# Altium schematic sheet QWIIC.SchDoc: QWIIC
size A3; Author: Silvio Navaretti; CompanyName: ARDUINO; DrawnBy: Silvio Navaretti; Engineer: Silvio Navaretti; Organization: ARDUINO; SheetNumber: 13; SheetTotal: 51; RevAuthor: Silvio Navaretti
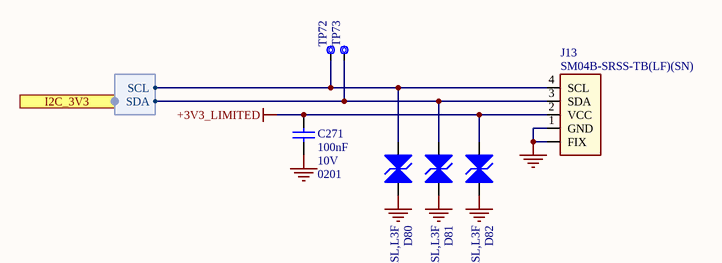
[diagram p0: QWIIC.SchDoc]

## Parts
C271  value 100nF  Voltage: 10V  Case Code (Imperial): 0201  [CAP-0201]  (hidden comment: CL03A104KP3NNNC)
D80  DF2B7ASL,L3F  [DF2B7ASL,L3F]
D81  DF2B7ASL,L3F  [DF2B7ASL,L3F]
D82  DF2B7ASL,L3F  [DF2B7ASL,L3F]
J13  SM04B-SRSS-TB(LF)(SN)  [SM04B-SRSS-TB(LF)(SN)-Footprint-1]
TP72  Test point 1.00mm  [TP-1.00MM]  (value not drawn)  (no BOM)
TP73  Test point 1.00mm  [TP-1.00MM]  (value not drawn)  (no BOM)

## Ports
I2C_3V3 (harness I2C)

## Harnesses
I2C: SDA, SCL

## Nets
+3V3_LIMITED: C271.2 D82.2(A2) J13.2(VCC)
GND: C271.1 D80.1(A1) D81.1(A1) D82.1(A1) J13.1(GND) J13.FIX
NetD80_2: D80.2(A2) J13.4(SCL) TP72.X ; port I2C_3V3.SCL
NetD81_2: D81.2(A2) J13.3(SDA) TP73.X ; port I2C_3V3.SDA

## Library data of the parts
C271 = C0113-A.6: CAP CHIP 0201 100nF 10% 10V X5R; Manufacturer: Samsung Electro-Mechanics; Code Arduino: C0113
D80-D82 = D0099-5: TVS BIDIRECTIONAL SMD Vr 5.5V, Vbr min 5.8V, 0.62x0.32mm; Manufacturer: TOSHIBA; Vforward max: 0V; Ireverse max: 1µA; Power max: 80W; Code Arduino: D0099; Vreverse max: 20V
J13 = J0005-A.3: CONN JST SH 1mm 4POS HORIZONTAL TIN QWIIC; Code Arduino: J0005
TP72 TP73 = UT0013-A.6: Part Number: This is not a component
